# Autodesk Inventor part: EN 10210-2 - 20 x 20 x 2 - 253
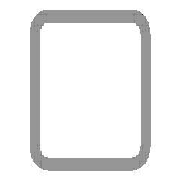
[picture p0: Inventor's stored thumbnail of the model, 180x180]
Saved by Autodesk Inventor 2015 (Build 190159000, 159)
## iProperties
Created: 2015-05
Part Number: EN 10210-2 - 20 x 20 x 2 - 253
Material: Steel, Mild
Description: Tube
Document SubType Name: Modeling
Standard: DIN
Designer: TREINA6
Standard Revision: 1997
Standards Organization: DIN
Language: en-US
Size Designation: 20 x 20 x 2
Categories: <MemberInstance><Categories><Category DisplayName="Structural Shapes" InternalName="089c4875-fa83-4c05-b084-43b9cc11f5ed" Mnemonic="GRDR"><CategoryParameter Dis
Stock Number: 20 x 20 x 2
Density: 7.85 g/cm^3
Appearance: Semi-Polished
_CCFamilyMember: 1
_CCFamilyDisplayName: DIN EN 10210-2 (Square) - Tube
_FrameMemberDoc: Frame Member File
_Version: 15.0.0
_GetPNFromCC: 1
IsCustomPart: 1
Author: TREINA6
G_L: 253,000 mm
G_W: 20,000 mm
G_H: 20,000 mm
+9808EFAD-8F49-4AFE-891C-7ED121EBB028+CUTDETAIL1: Miter 45,00 deg
+BB4E3DC9-09CA-4539-8D1D-C4E5F17BFB93+CUTDETAIL2: Miter 45,00 deg
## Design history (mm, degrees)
node "Start plane"
node "End plane"
sketch "Sketch"
  geometry: L1 (-10, -7)-(-10, 7); L2 (-7, 10)-(7, 10); L3 (10, 7)-(10, -7); L4 (7, -10)-(-7, -10); L5 (-7, 8)-(7, 8); L6 (8, 7)-(8, -7); L7 (7, -8)-(-7, -8); L8 (-8, -7)-(-8, 7); L9 (0, 14.87)-(0, -14.87) reference; L10 (-14.87, 0)-(14.87, 0) reference; A1 r 3 centre (-7, -7) between (-10, -7) and (-7, -10); A2 r 3 centre (-7, 7) between (-7, 10) and (-10, 7); A3 r 3 centre (7, 7) between (10, 7) and (7, 10); A4 r 3 centre (7, -7) between (7, -10) and (10, -7); A5 r 1 centre (-7, 7) between (-7, 8) and (-8, 7); A6 r 1 centre (7, 7) between (8, 7) and (7, 8); A7 r 1 centre (7, -7) between (7, -8) and (8, -7); A8 r 1 centre (-7, -7) between (-8, -7) and (-7, -8)
  constraints: 16 end point, 16 point on circle, 8 centre point, 8 tangent, 4 parallel, 3 equal radius, 2 perpendicular, 7 other
  dimensions: "d7" = 3 radius of A1 (= G_IR); "d10" = 20 distance between parallel lines of L2 L4 (= G_H); "d11" = 20 distance between parallel lines of L1 L3 (= G_W); "d12" = 2 distance between parallel lines of L3 L6 (= G_T); "d15" = 10 distance between parallel lines of L2 L10 (= 0.5 x d10); "d16" = 10 distance between parallel lines of L9 L3 (= 0.5 x d11)
extrude "Body" new body sketch "Sketch" stored distance "d3" = 253 (= G_L); taper "d4" = 0 deg
node "Driven Length"
  sketch "Sketch3"
    geometry: L1 (0, 0)-(10, 0) reference
    constraints: 2 end point, 1 horizontal
  workplane "Work Plane3"
  sketch "Sketch4"
    geometry: L1 (-2, 0)-(12, 0) reference; L2 (-2, 253)-(12, 253) reference
    dimensions: "d18" = 253 distance between parallel lines of L1 L2 (derived)
workplane "Work Plane4"
split "Split1"
workplane "Work Plane5"
split "Split2"
body "Solid1"
other parameters: "G_W" = 20 [user parameter; used in 1 equation term], "G_H" = 20 [user parameter; used in 1 equation term], "G_T" = 2 [user parameter; used in 1 equation term], "G_IR" = 3 [user parameter; used in 1 equation term], "G_L" = 253 (= d18) [user parameter; used in 1 equation term], "G_OFFSET_START" = 0 [user parameter; used in 1 equation term], "G_OFFSET_END" = 0 [user parameter; used in 1 equation term], "d13" = 0 (computed from G_OFFSET_START), "d14" = 253 (= G_OFFSET_END + B_L), "B_L" = 253 [user parameter; used in 1 equation term], "d17" = 90 deg
